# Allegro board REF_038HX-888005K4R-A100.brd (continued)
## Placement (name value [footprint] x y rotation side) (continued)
UNK2RP9  0-5-S4  [R0402]  213.98 216.67 180 bottom
UNK2RP10  0-5-S4  [R0402]  209.43 223.09 270 bottom
UNK2RP11  0-5-S4  [R0402]  202.16 223.09 270 bottom
UNK2RP12  0-5-S4  [R0402]  197.86 218.83 0 bottom
UNK2RT1  10K-1-S4  [R0402]  228.07 244.22 0 top
UNK2RT2  10K-1-S4  [R0402]  228.07 245.49 0 top
UNK2RT3  10K-1-S4  [R0402]  228.07 241.81 180 top
UNK2RT4  10K-1-S4  [R0402]  228.07 240.67 180 top
UNK2RT5  NC/10K-1-S4  [R0402]  228.07 242.95 180 top
UNK2RT6  NC/10K-1-S4  [R0402]  239.63 245.49 180 top
UNK2RT7  NC/10K-1-S4  [R0402]  239.63 242.95 180 top
UNK2RT8  NC/10K-1-S4  [R0402]  239.63 241.68 180 top
UNK2RT9  RTD-100-S8  [R0805]  229.15 205.62 90 top
UNK2RT10  0-5-S8  [R0805]  229.13 201.86 90 top
UNK2S1_I2C  HDR-4X1-MR-A  [JP_4P_100_R90_V1]  264 157.51 0 top
UNK2S1_RST_N  HDR-2X1-M  [JP_2P_100]  258.5 194.46 180 bottom
UNK2SK1  UA2-5NJ-A-V3  [RL_NECUA2_5V_V3]  252.24 183.98 270 bottom
UNK2SK2  UA2-5NJ-A-V3  [RL_NECUA2_5V_V3]  268.75 183.98 270 bottom
UNK2TP_AUXVCC  TP01  [TP_040_T]  47.18 295.44 180 top
UNK2TP_AVDD11_RX  TP01  [TP_040_T]  19.24 284.81 180 top
UNK2TP_AVDD11_XTAL  TP01  [TP_040_T]  45.28 262.58 0 top
UNK2TP_AVDD18_RX  TP01  [TP_040_T]  28.97 284.81 0 top
UNK2TP_PLL_M_VDD33  TP01  [TP_040_T]  45.28 244.17 0 top
UNK2TP_PLL_TX_VDD33  TP01  [TP_040_T]  35.55 244.17 180 top
UNK2TP_VCC3V3  TP01  [TP_040_T]  35.47 295.51 180 top
UNK2TP_VDD_IO_33  TP01  [TP_040_T]  35.55 284.81 180 top
UNK2TP_VDD_TXREG_33_B  TP01  [TP_040_T]  28.97 244.17 0 top
UNK2TP_VDD_TXREG_33_T  TP01  [TP_040_T]  19.24 244.17 180 top
UNK2TP_VDDA_33_LV  TP01  [TP_040_T]  45.28 284.81 0 top
UNK2TP_VDDC_11  TP01  [TP_040_T]  28.97 223.85 0 top
UNK2TP_VDDTXPST_11_B  TP01  [TP_040_T]  28.97 264.49 0 top
UNK2TP_VDDTXPST_11_T  TP01  [TP_040_T]  19.24 264.49 180 top
UNK2TP_XTAL_IN  TP01  [TP_040_T]  182.86 243.18 0 top
UNK2TP_XTAL_OUT  TP01  [TP_040_T]  182.86 248.48 0 top
UNK2U1  SOLDER-DIP8-SOCKET  [DIP8_300X100_RLPIN]  258.26 176.56 180 bottom
UNK2U2  SOLDER-DIP8-SOCKET  [DIP8_300X100_RLPIN]  277.97 176.56 180 bottom
UNK2UT1  ADT7410TRZ-SO8  [SO8_244X127MM]  233.92 243.59 0 top
UNK2Y1  XTAL27M-S2520-ABRACON-10P  [XTAL_2X2P5MM_4P]  174.77 246.4 270 bottom
UNK2Y2  NC/XTAL27M-S3225-TXC-10P  [XTAL_3P2X2P5MM_4P_TXC_0201]  174.77 246.4 270 bottom
UNK038HX-888005K4R-A100  REF-CODE-PCB  [PCB_CODE]  -1.03 116.16 0 top
UNK980HX-888005-KBH-  REF-CODE-PCB  [PCB_CODE]  -17 217.75 0 top
UT1  ADT7410TRZ-SO8  [SO8_244X127MM]  153.92 243.59 0 top
UT_UP5V  TP01  [TP_040_T]  20.37 142.21 270 top
UTL1  V93K_UTL  [PG_VG93K_F_G3UTI1]  35.83 16.51 0 top
UTL2  V93K_UTL  [PG_VG93K_F_G1UTI2]  183.15 16.51 0 top
UTL3  V93K_UTL  [PG_VG93K_F_G2UTI3]  256.81 412.75 0 top
UTL4  V93K_UTL  [PG_VG93K_F_G8UTI4]  109.49 412.75 0 top
Y1  XTAL27M-S2520-ABRACON-10P  [XTAL_2X2P5MM_4P]  94.77 246.4 270 bottom
Y2  NC/XTAL27M-S3225-TXC-10P  [XTAL_3P2X2P5MM_4P_TXC_0201]  94.77 246.4 270 bottom

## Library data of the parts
2SH1-2SH28 SB1-SB3 SB8 SH1-SH28 = SHORT: User Part Number: PNXXXXXXXXXX; Tolerance: TOL
BD29-BD40 = BD120-3A-S8: User Part Number: PNXXXXXXXXXX; Tolerance: TOL
BR902 = 330-1-S4: User Part Number: PNXXXXXXXXXX; Tolerance: TOL
C3 C4 C7-C9 CB1 CB3 CB5 CB7 CB19 CT1 UNK2C3 UNK2C4 UNK2C7-UNK2C9 UNK2CT1 = 0.1U-16-X-S4-MU: User Part Number: PNXXXXXXXXXX; Tolerance: TOL
C5 C6 UNK2C5 UNK2C6 = 22P-50-N-S4-AVX: User Part Number: PNXXXXXXXXXX; Tolerance: TOL
CA1 CA3 CA5 CA7 CA9 CA11 CA14 CA16 CA18 CA20-CA29 CA31 CA32 CA34 CA35 CA37 CA38 CA40 UNK2CA1 UNK2CA3 UNK2CA5 UNK2CA7 UNK2CA9 UNK2CA11 UNK2CA14 UNK2CA16 UNK2CA18 UNK2CA20-UNK2CA29 UNK2CA31 UNK2CA32 UNK2CA34 UNK2CA35 UNK2CA37 UNK2CA38 UNK2CA40 = 10U-10-X6S-S6-MU: User Part Number: PNXXXXXXXXXX; Tolerance: TOL
CA2 CA4 CA6 CA8 CA10 CA12 CA13 CA15 CA17 CA19 CA30 CA33 CA36 CA39 UNK2CA2 UNK2CA4 UNK2CA6 UNK2CA8 UNK2CA10 UNK2CA12 UNK2CA13 UNK2CA15 UNK2CA17 UNK2CA19 UNK2CA30 UNK2CA33 UNK2CA36 UNK2CA39 = 47U-10-X5R-S8-TDK: User Part Number: PNXXXXXXXXXX; Tolerance: TOL
CB2 CB4 CB6 CB8 = 10U-25-X-S6: User Part Number: PNXXXXXXXXXX; Tolerance: TOL
CC1 CC4 CC6-CC9 CC11 CC13 CC19 CC22 CC25-CC37 CC39 UNK2CC1 UNK2CC4 UNK2CC6-UNK2CC9 UNK2CC11 UNK2CC13 UNK2CC19 UNK2CC22 UNK2CC25-UNK2CC37 UNK2CC39 = 0.47U-10-X6S-S2-TY: User Part Number: PNXXXXXXXXXX; Tolerance: TOL
CC2 CC20 CC23 UNK2CC2 UNK2CC20 UNK2CC23 = 4.7U-10-X6T-S4-MU: User Part Number: PNXXXXXXXXXX; Tolerance: TOL
CC15-CC17 CC38 CC40-CC42 UNK2CC15-UNK2CC17 UNK2CC38 UNK2CC40-UNK2CC42 = 4.7U-2.5-X6S-S2-MU: User Part Number: PNXXXXXXXXXX; Tolerance: TOL
CD1 CD3-CD25 UNK2CD1 UNK2CD3-UNK2CD25 = 0.1U-10-X7R-S2-MU: User Part Number: PNXXXXXXXXXX; Tolerance: TOL
CSDPS225 CSDPS229 CSDPS425 CSDPS429 = V93K_CSDPS_DPS32: User Part Number: PNXXXXXXXXXX; Tolerance: TOL
D101/D501 D105/D505 = V93K_PS1600_HD: User Part Number: PNXXXXXXXXXX; Tolerance: TOL
D102-D104 D106-D124 D226-D228 D230-D232 D301 D302 D305 D306 D426-D428 D430-D432 = V93K_CH: Tolerance: TOL; User Part Number: PNXXXXXXXXXX
DPS1-DPS3 DPS8 = V93K_DPS: Tolerance: TOL; User Part Number: PNXXXXXXXXXX
FD1-FD8 = FD_040_V2: Tolerance: TOL; User Part Number: PNXXXXXXXXXX
GND1-GND14 SK1_2-SK1_7 SK2_2-SK2_7 TP_AUXVCC TP_AVDD11_RX TP_AVDD11_XTAL TP_AVDD18_RX TP_PLL_M_VDD33 TP_PLL_TX_VDD33 TP_VCC3V3 TP_VDD_IO_33 TP_VDD_TXREG_33_B TP_VDD_TXREG_33_T TP_VDDA_33_LV TP_VDDC_11 TP_VDDTXPST_11_B TP_VDDTXPST_11_T TP_XTAL_IN TP_XTAL_OUT UNK1SK1_2-UNK1SK1_7 UNK1SK2_2-UNK1SK2_7 UNK2GND1-UNK2GND14 UNK2TP_AUXVCC UNK2TP_AVDD11_RX UNK2TP_AVDD11_XTAL UNK2TP_AVDD18_RX UNK2TP_PLL_M_VDD33 UNK2TP_PLL_TX_VDD33 UNK2TP_VCC3V3 UNK2TP_VDD_IO_33 UNK2TP_VDD_TXREG_33_B UNK2TP_VDD_TXREG_33_T UNK2TP_VDDA_33_LV UNK2TP_VDDC_11 UNK2TP_VDDTXPST_11_B UNK2TP_VDDTXPST_11_T UNK2TP_XTAL_IN UNK2TP_XTAL_OUT UT_UP5V = TP01: Tolerance: TOL; User Part Number: PNXXXXXXXXXX
HX8880-F05 LQFP176-20X20-P0.4 = REF-CODE-CHIP
J1 J4 J5 S1_RST_N UNK2J1 UNK2J4 UNK2J5 UNK2S1_RST_N = HDR-2X1-M: Tolerance: TOL; User Part Number: PNXXXXXXXXXX
J2 J3 UNK2J2 UNK2J3 = HDR-3X1-M: Tolerance: TOL; User Part Number: PNXXXXXXXXXX
JG_220919AA01 JG_220919AA02 = REF-CODE-SOCKET
K1-K8 K11 K16 K17 K21-K27 K29 K30 UNK2K1-UNK2K8 UNK2K11 UNK2K16 UNK2K17 UNK2K21-UNK2K27 UNK2K29 UNK2K30 = G6K-2F-RF-5V-A: Tolerance: TOL; User Part Number: PNXXXXXXXXXX
K9 K10 K12-K15 K19 K20 K28 K33 SK1 SK2 UNK2K9 UNK2K10 UNK2K12-UNK2K15 UNK2K19 UNK2K20 UNK2K28 UNK2K33 UNK2SK1 UNK2SK2 = UA2-5NJ-A-V3: Tolerance: TOL; User Part Number: PNXXXXXXXXXX
K18 UNK2K18 = UB2-5NU-B: Tolerance: TOL; User Part Number: PNXXXXXXXXXX
K31 K34 K36 K37 K39 K40 K42 UNK2K31 UNK2K34 UNK2K36 UNK2K37 UNK2K39 UNK2K40 UNK2K42 = EC2-5NJ-A: Tolerance: TOL; User Part Number: PNXXXXXXXXXX
LD902 = LDG-2-S8: User Part Number: PNXXXXXXXXXX; Tolerance: TOL
LOGO1 = LOGO_KT_KSMT
LOGO2 = LOGO_HX_Himax
R1 R2 R6 UNK2R1 UNK2R2 UNK2R6 = 1M-1-S4: User Part Number: PNXXXXXXXXXX; Tolerance: TOL
R3 R4 R85 UNK2R3 UNK2R4 UNK2R85 = 100K-1-S4: User Part Number: PNXXXXXXXXXX; Tolerance: TOL
R5 R118 R125-R130 R133 RP1-RP12 UNK2R5 UNK2R118 UNK2R125-UNK2R130 UNK2R133 UNK2RP1-UNK2RP12 = 0-5-S4: User Part Number: PNXXXXXXXXXX; Tolerance: TOL
R7-R80 R100-R105 UNK2R7-UNK2R80 UNK2R100-UNK2R105 = 49.9-1-S4: User Part Number: PNXXXXXXXXXX; Tolerance: TOL
R82-R84 R86-R99 R119 R120 UNK2R82-UNK2R84 UNK2R86-UNK2R99 UNK2R119 UNK2R120 = 4.7K-1-S4-WA: User Part Number: PNXXXXXXXXXX; Tolerance: TOL
R117 UNK2R117 = 1K-1-S4: User Part Number: PNXXXXXXXXXX; Tolerance: TOL
R131 R132 UNK2R131 UNK2R132 = 50-0.1-S4-HF-VI: User Part Number: PNXXXXXXXXXX; Tolerance: TOL
RB1 RB2 = 10K-1-S6: User Part Number: PNXXXXXXXXXX; Tolerance: TOL
RT1-RT8 UNK2RT1-UNK2RT8 = 10K-1-S4: User Part Number: PNXXXXXXXXXX; Tolerance: TOL
RT9 UNK2RT9 = RTD-100-S8: User Part Number: PNXXXXXXXXXX; Tolerance: TOL
RT10 UNK2RT10 = 0-5-S8: User Part Number: PNXXXXXXXXXX; Tolerance: TOL
S1_I2C UNK2S1_I2C = HDR-4X1-MR-A: Tolerance: TOL; User Part Number: PNXXXXXXXXXX
SCREW1 = V93KHSCREW: Tolerance: TOL; User Part Number: PNXXXXXXXXXX
SITE1 SITE2 = CU/HX8880-F05-LQFP176-20X20: User Part Number: PNXXXXXXXXXX; Tolerance: TOL
SKB1 = V93K_SKB_140X140MM: Tolerance: TOL; User Part Number: PNXXXXXXXXXX
SW1 = SW-TACTILE-1-D4.5: Tolerance: TOL; User Part Number: PNXXXXXXXXXX
TPL1-TPL20 = TPL01: Tolerance: TOL; User Part Number: PNXXXXXXXXXX
U1 U2 UNK2U1 UNK2U2 = MX25V4006EM1I-13G-SO8: User Part Number: PNXXXXXXXXXX; Tolerance: TOL
UB1 = AT24C08-D: User Part Number: PNXXXXXXXXXX; Tolerance: TOL
UNK2UT1 UT1 = ADT7410: Tolerance: TOL; User Part Number: PNXXXXXXXXXX
UNK2Y1 Y1 = XTAL27M-S2520-ABRACON-10P: User Part Number: PNXXXXXXXXXX; Tolerance: TOL
UNK2Y2 Y2 = XTAL27M-S3225-TXC-10P: User Part Number: PNXXXXXXXXXX; Tolerance: TOL
UNK038HX-888005K4R-A100 UNK980HX-888005-KBH- = REF-CODE-PCB
UTL1-UTL4 = V93K_UTL: User Part Number: PNXXXXXXXXXX; Tolerance: TOL

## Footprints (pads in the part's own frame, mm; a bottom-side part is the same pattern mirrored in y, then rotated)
C0201
  rect 0.305x0.356 smd: 1(-0.3,0) 2(0.3,0)
C0402
  custom 0.15x0.15 smd: 1(-0.5,0) 2(0.5,0)
C0603
  rect 0.889x0.889 smd: 1(-0.85,0) 2(0.85,0)
C0805
  rect 1.118x1.372 smd: 1(-0.95,0) 2(0.95,0)
CHIP_CODE
  round 0.051 smd: 1(0,0)
DEFAULT_SHORT_SMALL
  custom 0.07x0.07 smd: 1(-0.5,0) 2(0.5,0)
DIP8_300X100_RLPIN
  rect 1.524x1.524 hole 1.041: 1(0,0)
  round 1.524 hole 1.041: 2(0,-2.54) 3(0,-5.08) 4(0,-7.62) 5(7.62,-7.62) 6(7.62,-5.08) 7(7.62,-2.54) 8(7.62,0)
FB0805
  rect 1.118x1.372 smd: 1(-0.965,0) 2(0.965,0)
FD_040_V2
  round 1.016 smd: 1(0,0)
JP_2P_100
  rect 1.524x1.524 hole 1.016: 1(0,0)
  round 1.524 hole 1.016: 2(0,2.54)
JP_3P_100
  rect 1.524x1.524 hole 1.016: 1(0,0)
  round 1.524 hole 1.016: 2(0,2.54) 3(0,5.08)
JP_4P_100_R90_V1
  rect 1.524x1.524 hole 1.016: 1(0,0)
  round 1.524 hole 1.016: 2(0,2.54) 3(0,5.08) 4(0,7.62)
LED_0805
  rect 1.118x1.372 smd: 1(0.95,0) 2(-0.95,0)
LOGO_HX_HIMAX
  round 0.051 smd: 1(0.831,1.487)
LOGO_KT_KSMT
  round 0.051 smd: 1(-0.711,-0.711)
PCB_CODE
  round 0.051 smd: 1(0,0)
PG_VG93K_F_G1D102
  round 1.778 hole 0.711: 01(-20.32,-1.27) 02(-17.78,1.27) 03(-15.24,-1.27) 04(-12.7,1.27) 05(-10.16,-1.27) 06(-7.62,1.27) 07(-5.08,-1.27) 08(-2.54,1.27) 09(0,-1.27) 10(2.54,1.27) 11(5.08,-1.27) 12(7.62,1.27) 13(10.16,-1.27) 14(12.7,1.27) 15(15.24,-1.27) 16(17.78,1.27) 17(20.32,-1.27)
  rect 1.778x1.778 hole 0.711: A1(-20.32,-3.81) A2(-17.78,-1.27) A3(-15.24,-3.81) A4(-12.7,-1.27) A5(-10.16,-3.81) A6(-7.62,-1.27) A7(-5.08,-3.81) A8(-2.54,-1.27) A9(0,-3.81) A10(2.54,-1.27) A11(5.08,-3.81) A12(7.62,-1.27) A13(10.16,-3.81) A14(12.7,-1.27) A15(15.24,-3.81) A16(17.78,-1.27) A17(20.32,-3.81) B1(-20.32,1.27) B2(-17.78,3.81) B3(-15.24,1.27) B4(-12.7,3.81) B5(-10.16,1.27) B6(-7.62,3.81) B7(-5.08,1.27) B8(-2.54,3.81) B9(0,1.27) B10(2.54,3.81) B11(5.08,1.27) B12(7.62,3.81) B13(10.16,1.27) B14(12.7,3.81) B15(15.24,1.27) B16(17.78,3.81) B17(20.32,1.27)
PG_VG93K_F_G1D103
  round 1.778 hole 0.711: 01(-20.32,-1.27) 02(-17.78,1.27) 03(-15.24,-1.27) 04(-12.7,1.27) 05(-10.16,-1.27) 06(-7.62,1.27) 07(-5.08,-1.27) 08(-2.54,1.27) 09(0,-1.27) 10(2.54,1.27) 11(5.08,-1.27) 12(7.62,1.27) 13(10.16,-1.27) 14(12.7,1.27) 15(15.24,-1.27) 16(17.78,1.27) 17(20.32,-1.27)
  rect 1.778x1.778 hole 0.711: A1(-20.32,-3.81) A2(-17.78,-1.27) A3(-15.24,-3.81) A4(-12.7,-1.27) A5(-10.16,-3.81) A6(-7.62,-1.27) A7(-5.08,-3.81) A8(-2.54,-1.27) A9(0,-3.81) A10(2.54,-1.27) A11(5.08,-3.81) A12(7.62,-1.27) A13(10.16,-3.81) A14(12.7,-1.27) A15(15.24,-3.81) A16(17.78,-1.27) A17(20.32,-3.81) B1(-20.32,1.27) B2(-17.78,3.81) B3(-15.24,1.27) B4(-12.7,3.81) B5(-10.16,1.27) B6(-7.62,3.81) B7(-5.08,1.27) B8(-2.54,3.81) B9(0,1.27) B10(2.54,3.81) B11(5.08,1.27) B12(7.62,3.81) B13(10.16,1.27) B14(12.7,3.81) B15(15.24,1.27) B16(17.78,3.81) B17(20.32,1.27)
PG_VG93K_F_G1D104
  round 1.778 hole 0.711: 01(-20.32,-1.27) 02(-17.78,1.27) 03(-15.24,-1.27) 04(-12.7,1.27) 05(-10.16,-1.27) 06(-7.62,1.27) 07(-5.08,-1.27) 08(-2.54,1.27) 09(0,-1.27) 10(2.54,1.27) 11(5.08,-1.27) 12(7.62,1.27) 13(10.16,-1.27) 14(12.7,1.27) 15(15.24,-1.27) 16(17.78,1.27) 17(20.32,-1.27)
  rect 1.778x1.778 hole 0.711: A1(-20.32,-3.81) A2(-17.78,-1.27) A3(-15.24,-3.81) A4(-12.7,-1.27) A5(-10.16,-3.81) A6(-7.62,-1.27) A7(-5.08,-3.81) A8(-2.54,-1.27) A9(0,-3.81) A10(2.54,-1.27) A11(5.08,-3.81) A12(7.62,-1.27) A13(10.16,-3.81) A14(12.7,-1.27) A15(15.24,-3.81) A16(17.78,-1.27) A17(20.32,-3.81) B1(-20.32,1.27) B2(-17.78,3.81) B3(-15.24,1.27) B4(-12.7,3.81) B5(-10.16,1.27) B6(-7.62,3.81) B7(-5.08,1.27) B8(-2.54,3.81) B9(0,1.27) B10(2.54,3.81) B11(5.08,1.27) B12(7.62,3.81) B13(10.16,1.27) B14(12.7,3.81) B15(15.24,1.27) B16(17.78,3.81) B17(20.32,1.27)
PG_VG93K_F_G1D106
  round 1.778 hole 0.711: 01(-20.32,-1.27) 02(-17.78,1.27) 03(-15.24,-1.27) 04(-12.7,1.27) 05(-10.16,-1.27) 06(-7.62,1.27) 07(-5.08,-1.27) 08(-2.54,1.27) 09(0,-1.27) 10(2.54,1.27) 11(5.08,-1.27) 12(7.62,1.27) 13(10.16,-1.27) 14(12.7,1.27) 15(15.24,-1.27) 16(17.78,1.27) 17(20.32,-1.27)
  rect 1.778x1.778 hole 0.711: A1(-20.32,-3.81) A2(-17.78,-1.27) A3(-15.24,-3.81) A4(-12.7,-1.27) A5(-10.16,-3.81) A6(-7.62,-1.27) A7(-5.08,-3.81) A8(-2.54,-1.27) A9(0,-3.81) A10(2.54,-1.27) A11(5.08,-3.81) A12(7.62,-1.27) A13(10.16,-3.81) A14(12.7,-1.27) A15(15.24,-3.81) A16(17.78,-1.27) A17(20.32,-3.81) B1(-20.32,1.27) B2(-17.78,3.81) B3(-15.24,1.27) B4(-12.7,3.81) B5(-10.16,1.27) B6(-7.62,3.81) B7(-5.08,1.27) B8(-2.54,3.81) B9(0,1.27) B10(2.54,3.81) B11(5.08,1.27) B12(7.62,3.81) B13(10.16,1.27) B14(12.7,3.81) B15(15.24,1.27) B16(17.78,3.81) B17(20.32,1.27)
PG_VG93K_F_G1D107
  round 1.778 hole 0.711: 01(-20.32,-1.27) 02(-17.78,1.27) 03(-15.24,-1.27) 04(-12.7,1.27) 05(-10.16,-1.27) 06(-7.62,1.27) 07(-5.08,-1.27) 08(-2.54,1.27) 09(0,-1.27) 10(2.54,1.27) 11(5.08,-1.27) 12(7.62,1.27) 13(10.16,-1.27) 14(12.7,1.27) 15(15.24,-1.27) 16(17.78,1.27) 17(20.32,-1.27)
  rect 1.778x1.778 hole 0.711: A1(-20.32,-3.81) A2(-17.78,-1.27) A3(-15.24,-3.81) A4(-12.7,-1.27) A5(-10.16,-3.81) A6(-7.62,-1.27) A7(-5.08,-3.81) A8(-2.54,-1.27) A9(0,-3.81) A10(2.54,-1.27) A11(5.08,-3.81) A12(7.62,-1.27) A13(10.16,-3.81) A14(12.7,-1.27) A15(15.24,-3.81) A16(17.78,-1.27) A17(20.32,-3.81) B1(-20.32,1.27) B2(-17.78,3.81) B3(-15.24,1.27) B4(-12.7,3.81) B5(-10.16,1.27) B6(-7.62,3.81) B7(-5.08,1.27) B8(-2.54,3.81) B9(0,1.27) B10(2.54,3.81) B11(5.08,1.27) B12(7.62,3.81) B13(10.16,1.27) B14(12.7,3.81) B15(15.24,1.27) B16(17.78,3.81) B17(20.32,1.27)
PG_VG93K_F_G1D108
  round 1.778 hole 0.711: 01(-20.32,-1.27) 02(-17.78,1.27) 03(-15.24,-1.27) 04(-12.7,1.27) 05(-10.16,-1.27) 06(-7.62,1.27) 07(-5.08,-1.27) 08(-2.54,1.27) 09(0,-1.27) 10(2.54,1.27) 11(5.08,-1.27) 12(7.62,1.27) 13(10.16,-1.27) 14(12.7,1.27) 15(15.24,-1.27) 16(17.78,1.27) 17(20.32,-1.27)
  rect 1.778x1.778 hole 0.711: A1(-20.32,-3.81) A2(-17.78,-1.27) A3(-15.24,-3.81) A4(-12.7,-1.27) A5(-10.16,-3.81) A6(-7.62,-1.27) A7(-5.08,-3.81) A8(-2.54,-1.27) A9(0,-3.81) A10(2.54,-1.27) A11(5.08,-3.81) A12(7.62,-1.27) A13(10.16,-3.81) A14(12.7,-1.27) A15(15.24,-3.81) A16(17.78,-1.27) A17(20.32,-3.81) B1(-20.32,1.27) B2(-17.78,3.81) B3(-15.24,1.27) B4(-12.7,3.81) B5(-10.16,1.27) B6(-7.62,3.81) B7(-5.08,1.27) B8(-2.54,3.81) B9(0,1.27) B10(2.54,3.81) B11(5.08,1.27) B12(7.62,3.81) B13(10.16,1.27) B14(12.7,3.81) B15(15.24,1.27) B16(17.78,3.81) B17(20.32,1.27)
PG_VG93K_F_G1D301
  round 1.778 hole 0.711: 01(-20.32,-1.27) 03(-15.24,-1.27) 05(-10.16,-1.27) 07(-5.08,-1.27) 09(0,-1.27) 11(5.08,-1.27) 13(10.16,-1.27) 15(15.24,-1.27) 17(20.32,-1.27)
  round 0.66 hole 0.356: 02(-17.78,1.27) 04(-12.7,1.27) 06(-7.62,1.27) 08(-2.54,1.27) 10(2.54,1.27) 12(7.62,1.27) 14(12.7,1.27) 16(17.78,1.27)
  rect 1.778x1.778 hole 0.711: A1(-20.32,-3.81) A2(-17.78,-1.27) A3(-15.24,-3.81) A4(-12.7,-1.27) A5(-10.16,-3.81) A6(-7.62,-1.27) A7(-5.08,-3.81) A8(-2.54,-1.27) A9(0,-3.81) A10(2.54,-1.27) A11(5.08,-3.81) A12(7.62,-1.27) A13(10.16,-3.81) A14(12.7,-1.27) A15(15.24,-3.81) A16(17.78,-1.27) A17(20.32,-3.81) B1(-20.32,1.27) B2(-17.78,3.81) B3(-15.24,1.27) B4(-12.7,3.81) B5(-10.16,1.27) B6(-7.62,3.81) B7(-5.08,1.27) B8(-2.54,3.81) B9(0,1.27) B10(2.54,3.81) B11(5.08,1.27) B12(7.62,3.81) B13(10.16,1.27) B14(12.7,3.81) B15(15.24,1.27) B16(17.78,3.81) B17(20.32,1.27)
PG_VG93K_F_G1D302
  round 1.778 hole 0.711: 01(-20.32,-1.27) 02(-17.78,1.27) 03(-15.24,-1.27) 04(-12.7,1.27) 05(-10.16,-1.27) 06(-7.62,1.27) 07(-5.08,-1.27) 08(-2.54,1.27) 09(0,-1.27) 10(2.54,1.27) 11(5.08,-1.27) 12(7.62,1.27) 13(10.16,-1.27) 14(12.7,1.27) 15(15.24,-1.27) 16(17.78,1.27) 17(20.32,-1.27)
  rect 1.778x1.778 hole 0.711: A1(-20.32,-3.81) A2(-17.78,-1.27) A3(-15.24,-3.81) A4(-12.7,-1.27) A5(-10.16,-3.81) A6(-7.62,-1.27) A7(-5.08,-3.81) A8(-2.54,-1.27) A9(0,-3.81) A10(2.54,-1.27) A11(5.08,-3.81) A12(7.62,-1.27) A13(10.16,-3.81) A14(12.7,-1.27) A15(15.24,-3.81) A16(17.78,-1.27) A17(20.32,-3.81) B1(-20.32,1.27) B2(-17.78,3.81) B3(-15.24,1.27) B4(-12.7,3.81) B5(-10.16,1.27) B6(-7.62,3.81) B7(-5.08,1.27) B8(-2.54,3.81) B9(0,1.27) B10(2.54,3.81) B11(5.08,1.27) B12(7.62,3.81) B13(10.16,1.27) B14(12.7,3.81) B15(15.24,1.27) B16(17.78,3.81) B17(20.32,1.27)
PG_VG93K_F_G1D305
  round 1.778 hole 0.711: 01(-20.32,-1.27) 03(-15.24,-1.27) 05(-10.16,-1.27) 07(-5.08,-1.27) 09(0,-1.27) 11(5.08,-1.27) 13(10.16,-1.27) 15(15.24,-1.27) 17(20.32,-1.27)
  round 0.66 hole 0.356: 02(-17.78,1.27) 04(-12.7,1.27) 06(-7.62,1.27) 08(-2.54,1.27) 10(2.54,1.27) 12(7.62,1.27) 14(12.7,1.27) 16(17.78,1.27)
  rect 1.778x1.778 hole 0.711: A1(-20.32,-3.81) A2(-17.78,-1.27) A3(-15.24,-3.81) A4(-12.7,-1.27) A5(-10.16,-3.81) A6(-7.62,-1.27) A7(-5.08,-3.81) A8(-2.54,-1.27) A9(0,-3.81) A10(2.54,-1.27) A11(5.08,-3.81) A12(7.62,-1.27) A13(10.16,-3.81) A14(12.7,-1.27) A15(15.24,-3.81) A16(17.78,-1.27) A17(20.32,-3.81) B1(-20.32,1.27) B2(-17.78,3.81) B3(-15.24,1.27) B4(-12.7,3.81) B5(-10.16,1.27) B6(-7.62,3.81) B7(-5.08,1.27) B8(-2.54,3.81) B9(0,1.27) B10(2.54,3.81) B11(5.08,1.27) B12(7.62,3.81) B13(10.16,1.27) B14(12.7,3.81) B15(15.24,1.27) B16(17.78,3.81) B17(20.32,1.27)
PG_VG93K_F_G1D306
  round 1.778 hole 0.711: 01(-20.32,-1.27) 02(-17.78,1.27) 03(-15.24,-1.27) 04(-12.7,1.27) 05(-10.16,-1.27) 06(-7.62,1.27) 07(-5.08,-1.27) 08(-2.54,1.27) 09(0,-1.27) 10(2.54,1.27) 11(5.08,-1.27) 12(7.62,1.27) 13(10.16,-1.27) 14(12.7,1.27) 15(15.24,-1.27) 16(17.78,1.27) 17(20.32,-1.27)
  rect 1.778x1.778 hole 0.711: A1(-20.32,-3.81) A2(-17.78,-1.27) A3(-15.24,-3.81) A4(-12.7,-1.27) A5(-10.16,-3.81) A6(-7.62,-1.27) A7(-5.08,-3.81) A8(-2.54,-1.27) A9(0,-3.81) A10(2.54,-1.27) A11(5.08,-3.81) A12(7.62,-1.27) A13(10.16,-3.81) A14(12.7,-1.27) A15(15.24,-3.81) A16(17.78,-1.27) A17(20.32,-3.81) B1(-20.32,1.27) B2(-17.78,3.81) B3(-15.24,1.27) B4(-12.7,3.81) B5(-10.16,1.27) B6(-7.62,3.81) B7(-5.08,1.27) B8(-2.54,3.81) B9(0,1.27) B10(2.54,3.81) B11(5.08,1.27) B12(7.62,3.81) B13(10.16,1.27) B14(12.7,3.81) B15(15.24,1.27) B16(17.78,3.81) B17(20.32,1.27)
PG_VG93K_F_G1DPS1
  round 1.778 hole 0.711: A01(-20.32,-2.54) A02(-17.78,-2.54) A03(-15.24,-2.54) A04(-12.7,-2.54) A05(-10.16,-2.54) A06(-7.62,-2.54) A07(-5.08,-2.54) A08(-2.54,-2.54) A09(0,-2.54) A10(2.54,-2.54) A11(5.08,-2.54) A12(7.62,-2.54) A13(10.16,-2.54) A14(12.7,-2.54) A15(15.24,-2.54) A16(17.78,-2.54) A17(20.32,-2.54) B01(-20.32,0) B02(-17.78,0) B03(-15.24,0) B04(-12.7,0) B05(-10.16,0) B06(-7.62,0) B07(-5.08,0) B08(-2.54,0) B09(0,0) B10(2.54,0) B11(5.08,0) B12(7.62,0) B13(10.16,0) B14(12.7,0) B15(15.24,0) B16(17.78,0) B17(20.32,0) C01(-20.32,2.54) C02(-17.78,2.54) C03(-15.24,2.54) C04(-12.7,2.54) C05(-10.16,2.54) C06(-7.62,2.54) C07(-5.08,2.54) C08(-2.54,2.54) C09(0,2.54) C10(2.54,2.54) C11(5.08,2.54) C12(7.62,2.54) C13(10.16,2.54) C14(12.7,2.54) C15(15.24,2.54) C16(17.78,2.54) C17(20.32,2.54)
PG_VG93K_F_G1UTI2
  round 1.778 hole 0.711: A01(-20.32,-1.27) A02(-17.78,-1.27) A03(-15.24,-1.27) A04(-12.7,-1.27) A05(-10.16,-1.27) A06(-7.62,-1.27) A07(-5.08,-1.27) A08(-2.54,-1.27) A09(0,-1.27) A10(2.54,-1.27) A11(5.08,-1.27) A12(7.62,-1.27) A13(10.16,-1.27) A14(12.7,-1.27) A15(15.24,-1.27) A16(17.78,-1.27) A17(20.32,-1.27) B01(-20.32,1.27) B02(-17.78,1.27) B03(-15.24,1.27) B04(-12.7,1.27) B05(-10.16,1.27) B06(-7.62,1.27) B07(-5.08,1.27) B08(-2.54,1.27) B09(0,1.27) B10(2.54,1.27) B11(5.08,1.27) B12(7.62,1.27) B13(10.16,1.27) B14(12.7,1.27) B15(15.24,1.27) B16(17.78,1.27) B17(20.32,1.27)
PG_VG93K_F_G2D109
  round 1.778 hole 0.711: 01(20.32,1.27) 02(17.78,-1.27) 03(15.24,1.27) 04(12.7,-1.27) 05(10.16,1.27) 06(7.62,-1.27) 07(5.08,1.27) 08(2.54,-1.27) 09(0,1.27) 10(-2.54,-1.27) 11(-5.08,1.27) 12(-7.62,-1.27) 13(-10.16,1.27) 14(-12.7,-1.27) 15(-15.24,1.27) 16(-17.78,-1.27) 17(-20.32,1.27)
  rect 1.778x1.778 hole 0.711: A1(20.32,3.81) A2(17.78,1.27) A3(15.24,3.81) A4(12.7,1.27) A5(10.16,3.81) A6(7.62,1.27) A7(5.08,3.81) A8(2.54,1.27) A9(0,3.81) A10(-2.54,1.27) A11(-5.08,3.81) A12(-7.62,1.27) A13(-10.16,3.81) A14(-12.7,1.27) A15(-15.24,3.81) A16(-17.78,1.27) A17(-20.32,3.81) B1(20.32,-1.27) B2(17.78,-3.81) B3(15.24,-1.27) B4(12.7,-3.81) B5(10.16,-1.27) B6(7.62,-3.81) B7(5.08,-1.27) B8(2.54,-3.81) B9(0,-1.27) B10(-2.54,-3.81) B11(-5.08,-1.27) B12(-7.62,-3.81) B13(-10.16,-1.27) B14(-12.7,-3.81) B15(-15.24,-1.27) B16(-17.78,-3.81) B17(-20.32,-1.27)
PG_VG93K_F_G2D110
  round 1.778 hole 0.711: 01(20.32,1.27) 02(17.78,-1.27) 03(15.24,1.27) 04(12.7,-1.27) 05(10.16,1.27) 06(7.62,-1.27) 07(5.08,1.27) 08(2.54,-1.27) 09(0,1.27) 10(-2.54,-1.27) 11(-5.08,1.27) 12(-7.62,-1.27) 13(-10.16,1.27) 14(-12.7,-1.27) 15(-15.24,1.27) 16(-17.78,-1.27) 17(-20.32,1.27)
  rect 1.778x1.778 hole 0.711: A1(20.32,3.81) A2(17.78,1.27) A3(15.24,3.81) A4(12.7,1.27) A5(10.16,3.81) A6(7.62,1.27) A7(5.08,3.81) A8(2.54,1.27) A9(0,3.81) A10(-2.54,1.27) A11(-5.08,3.81) A12(-7.62,1.27) A13(-10.16,3.81) A14(-12.7,1.27) A15(-15.24,3.81) A16(-17.78,1.27) A17(-20.32,3.81) B1(20.32,-1.27) B2(17.78,-3.81) B3(15.24,-1.27) B4(12.7,-3.81) B5(10.16,-1.27) B6(7.62,-3.81) B7(5.08,-1.27) B8(2.54,-3.81) B9(0,-1.27) B10(-2.54,-3.81) B11(-5.08,-1.27) B12(-7.62,-3.81) B13(-10.16,-1.27) B14(-12.7,-3.81) B15(-15.24,-1.27) B16(-17.78,-3.81) B17(-20.32,-1.27)
PG_VG93K_F_G2D111
  round 1.778 hole 0.711: 01(20.32,1.27) 02(17.78,-1.27) 03(15.24,1.27) 04(12.7,-1.27) 05(10.16,1.27) 06(7.62,-1.27) 07(5.08,1.27) 08(2.54,-1.27) 09(0,1.27) 10(-2.54,-1.27) 11(-5.08,1.27) 12(-7.62,-1.27) 13(-10.16,1.27) 14(-12.7,-1.27) 15(-15.24,1.27) 16(-17.78,-1.27) 17(-20.32,1.27)
  rect 1.778x1.778 hole 0.711: A1(20.32,3.81) A2(17.78,1.27) A3(15.24,3.81) A4(12.7,1.27) A5(10.16,3.81) A6(7.62,1.27) A7(5.08,3.81) A8(2.54,1.27) A9(0,3.81) A10(-2.54,1.27) A11(-5.08,3.81) A12(-7.62,1.27) A13(-10.16,3.81) A14(-12.7,1.27) A15(-15.24,3.81) A16(-17.78,1.27) A17(-20.32,3.81) B1(20.32,-1.27) B2(17.78,-3.81) B3(15.24,-1.27) B4(12.7,-3.81) B5(10.16,-1.27) B6(7.62,-3.81) B7(5.08,-1.27) B8(2.54,-3.81) B9(0,-1.27) B10(-2.54,-3.81) B11(-5.08,-1.27) B12(-7.62,-3.81) B13(-10.16,-1.27) B14(-12.7,-3.81) B15(-15.24,-1.27) B16(-17.78,-3.81) B17(-20.32,-1.27)
PG_VG93K_F_G2D112
  round 1.778 hole 0.711: 01(20.32,1.27) 02(17.78,-1.27) 03(15.24,1.27) 04(12.7,-1.27) 05(10.16,1.27) 06(7.62,-1.27) 07(5.08,1.27) 08(2.54,-1.27) 09(0,1.27) 10(-2.54,-1.27) 11(-5.08,1.27) 12(-7.62,-1.27) 13(-10.16,1.27) 14(-12.7,-1.27) 15(-15.24,1.27) 16(-17.78,-1.27) 17(-20.32,1.27)
  rect 1.778x1.778 hole 0.711: A1(20.32,3.81) A2(17.78,1.27) A3(15.24,3.81) A4(12.7,1.27) A5(10.16,3.81) A6(7.62,1.27) A7(5.08,3.81) A8(2.54,1.27) A9(0,3.81) A10(-2.54,1.27) A11(-5.08,3.81) A12(-7.62,1.27) A13(-10.16,3.81) A14(-12.7,1.27) A15(-15.24,3.81) A16(-17.78,1.27) A17(-20.32,3.81) B1(20.32,-1.27) B2(17.78,-3.81) B3(15.24,-1.27) B4(12.7,-3.81) B5(10.16,-1.27) B6(7.62,-3.81) B7(5.08,-1.27) B8(2.54,-3.81) B9(0,-1.27) B10(-2.54,-3.81) B11(-5.08,-1.27) B12(-7.62,-3.81) B13(-10.16,-1.27) B14(-12.7,-3.81) B15(-15.24,-1.27) B16(-17.78,-3.81) B17(-20.32,-1.27)
PG_VG93K_F_G2D113
  round 1.778 hole 0.711: 01(20.32,1.27) 02(17.78,-1.27) 03(15.24,1.27) 04(12.7,-1.27) 05(10.16,1.27) 06(7.62,-1.27) 07(5.08,1.27) 08(2.54,-1.27) 09(0,1.27) 10(-2.54,-1.27) 11(-5.08,1.27) 12(-7.62,-1.27) 13(-10.16,1.27) 14(-12.7,-1.27) 15(-15.24,1.27) 16(-17.78,-1.27) 17(-20.32,1.27)
  rect 1.778x1.778 hole 0.711: A1(20.32,3.81) A2(17.78,1.27) A3(15.24,3.81) A4(12.7,1.27) A5(10.16,3.81) A6(7.62,1.27) A7(5.08,3.81) A8(2.54,1.27) A9(0,3.81) A10(-2.54,1.27) A11(-5.08,3.81) A12(-7.62,1.27) A13(-10.16,3.81) A14(-12.7,1.27) A15(-15.24,3.81) A16(-17.78,1.27) A17(-20.32,3.81) B1(20.32,-1.27) B2(17.78,-3.81) B3(15.24,-1.27) B4(12.7,-3.81) B5(10.16,-1.27) B6(7.62,-3.81) B7(5.08,-1.27) B8(2.54,-3.81) B9(0,-1.27) B10(-2.54,-3.81) B11(-5.08,-1.27) B12(-7.62,-3.81) B13(-10.16,-1.27) B14(-12.7,-3.81) B15(-15.24,-1.27) B16(-17.78,-3.81) B17(-20.32,-1.27)
PG_VG93K_F_G2D114
  round 1.778 hole 0.711: 01(20.32,1.27) 02(17.78,-1.27) 03(15.24,1.27) 04(12.7,-1.27) 05(10.16,1.27) 06(7.62,-1.27) 07(5.08,1.27) 08(2.54,-1.27) 09(0,1.27) 10(-2.54,-1.27) 11(-5.08,1.27) 12(-7.62,-1.27) 13(-10.16,1.27) 14(-12.7,-1.27) 15(-15.24,1.27) 16(-17.78,-1.27) 17(-20.32,1.27)
  rect 1.778x1.778 hole 0.711: A1(20.32,3.81) A2(17.78,1.27) A3(15.24,3.81) A4(12.7,1.27) A5(10.16,3.81) A6(7.62,1.27) A7(5.08,3.81) A8(2.54,1.27) A9(0,3.81) A10(-2.54,1.27) A11(-5.08,3.81) A12(-7.62,1.27) A13(-10.16,3.81) A14(-12.7,1.27) A15(-15.24,3.81) A16(-17.78,1.27) A17(-20.32,3.81) B1(20.32,-1.27) B2(17.78,-3.81) B3(15.24,-1.27) B4(12.7,-3.81) B5(10.16,-1.27) B6(7.62,-3.81) B7(5.08,-1.27) B8(2.54,-3.81) B9(0,-1.27) B10(-2.54,-3.81) B11(-5.08,-1.27) B12(-7.62,-3.81) B13(-10.16,-1.27) B14(-12.7,-3.81) B15(-15.24,-1.27) B16(-17.78,-3.81) B17(-20.32,-1.27)
PG_VG93K_F_G2D115
  round 1.778 hole 0.711: 01(20.32,1.27) 02(17.78,-1.27) 03(15.24,1.27) 04(12.7,-1.27) 05(10.16,1.27) 06(7.62,-1.27) 07(5.08,1.27) 08(2.54,-1.27) 09(0,1.27) 10(-2.54,-1.27) 11(-5.08,1.27) 12(-7.62,-1.27) 13(-10.16,1.27) 14(-12.7,-1.27) 15(-15.24,1.27) 16(-17.78,-1.27) 17(-20.32,1.27)
  rect 1.778x1.778 hole 0.711: A1(20.32,3.81) A2(17.78,1.27) A3(15.24,3.81) A4(12.7,1.27) A5(10.16,3.81) A6(7.62,1.27) A7(5.08,3.81) A8(2.54,1.27) A9(0,3.81) A10(-2.54,1.27) A11(-5.08,3.81) A12(-7.62,1.27) A13(-10.16,3.81) A14(-12.7,1.27) A15(-15.24,3.81) A16(-17.78,1.27) A17(-20.32,3.81) B1(20.32,-1.27) B2(17.78,-3.81) B3(15.24,-1.27) B4(12.7,-3.81) B5(10.16,-1.27) B6(7.62,-3.81) B7(5.08,-1.27) B8(2.54,-3.81) B9(0,-1.27) B10(-2.54,-3.81) B11(-5.08,-1.27) B12(-7.62,-3.81) B13(-10.16,-1.27) B14(-12.7,-3.81) B15(-15.24,-1.27) B16(-17.78,-3.81) B17(-20.32,-1.27)
PG_VG93K_F_G2D116
  round 1.778 hole 0.711: 01(20.32,1.27) 02(17.78,-1.27) 03(15.24,1.27) 04(12.7,-1.27) 05(10.16,1.27) 06(7.62,-1.27) 07(5.08,1.27) 08(2.54,-1.27) 09(0,1.27) 10(-2.54,-1.27) 11(-5.08,1.27) 12(-7.62,-1.27) 13(-10.16,1.27) 14(-12.7,-1.27) 15(-15.24,1.27) 16(-17.78,-1.27) 17(-20.32,1.27)
  rect 1.778x1.778 hole 0.711: A1(20.32,3.81) A2(17.78,1.27) A3(15.24,3.81) A4(12.7,1.27) A5(10.16,3.81) A6(7.62,1.27) A7(5.08,3.81) A8(2.54,1.27) A9(0,3.81) A10(-2.54,1.27) A11(-5.08,3.81) A12(-7.62,1.27) A13(-10.16,3.81) A14(-12.7,1.27) A15(-15.24,3.81) A16(-17.78,1.27) A17(-20.32,3.81) B1(20.32,-1.27) B2(17.78,-3.81) B3(15.24,-1.27) B4(12.7,-3.81) B5(10.16,-1.27) B6(7.62,-3.81) B7(5.08,-1.27) B8(2.54,-3.81) B9(0,-1.27) B10(-2.54,-3.81) B11(-5.08,-1.27) B12(-7.62,-3.81) B13(-10.16,-1.27) B14(-12.7,-3.81) B15(-15.24,-1.27) B16(-17.78,-3.81) B17(-20.32,-1.27)
PG_VG93K_F_G2DPS2
  round 1.778 hole 0.711: A01(20.32,2.54) A02(17.78,2.54) A03(15.24,2.54) A04(12.7,2.54) A05(10.16,2.54) A06(7.62,2.54) A07(5.08,2.54) A08(2.54,2.54) A09(0,2.54) A10(-2.54,2.54) A11(-5.08,2.54) A12(-7.62,2.54) A13(-10.16,2.54) A14(-12.7,2.54) A15(-15.24,2.54) A16(-17.78,2.54) A17(-20.32,2.54) B01(20.32,0) B02(17.78,0) B03(15.24,0) B04(12.7,0) B05(10.16,0) B06(7.62,0) B07(5.08,0) B08(2.54,0) B09(0,0) B10(-2.54,0) B11(-5.08,0) B12(-7.62,0) B13(-10.16,0) B14(-12.7,0) B15(-15.24,0) B16(-17.78,0) B17(-20.32,0) C01(20.32,-2.54) C02(17.78,-2.54) C03(15.24,-2.54) C04(12.7,-2.54) C05(10.16,-2.54) C06(7.62,-2.54) C07(5.08,-2.54) C08(2.54,-2.54) C09(0,-2.54) C10(-2.54,-2.54) C11(-5.08,-2.54) C12(-7.62,-2.54) C13(-10.16,-2.54) C14(-12.7,-2.54) C15(-15.24,-2.54) C16(-17.78,-2.54) C17(-20.32,-2.54)
PG_VG93K_F_G2UTI3
  round 1.778 hole 0.711: A01(20.32,1.27) A02(17.78,1.27) A03(15.24,1.27) A04(12.7,1.27) A05(10.16,1.27) A06(7.62,1.27) A07(5.08,1.27) A08(2.54,1.27) A09(0,1.27) A10(-2.54,1.27) A11(-5.08,1.27) A12(-7.62,1.27) A13(-10.16,1.27) A14(-12.7,1.27) A15(-15.24,1.27) A16(-17.78,1.27) A17(-20.32,1.27) B01(20.32,-1.27) B02(17.78,-1.27) B03(15.24,-1.27) B04(12.7,-1.27) B05(10.16,-1.27) B06(7.62,-1.27) B07(5.08,-1.27) B08(2.54,-1.27) B09(0,-1.27) B10(-2.54,-1.27) B11(-5.08,-1.27) B12(-7.62,-1.27) B13(-10.16,-1.27) B14(-12.7,-1.27) B15(-15.24,-1.27) B16(-17.78,-1.27) B17(-20.32,-1.27)
PG_VG93K_F_G3D117
  round 1.778 hole 0.711: 01(-20.32,-1.27) 02(-17.78,1.27) 03(-15.24,-1.27) 04(-12.7,1.27) 05(-10.16,-1.27) 06(-7.62,1.27) 07(-5.08,-1.27) 08(-2.54,1.27) 09(0,-1.27) 10(2.54,1.27) 11(5.08,-1.27) 12(7.62,1.27) 13(10.16,-1.27) 14(12.7,1.27) 15(15.24,-1.27) 16(17.78,1.27) 17(20.32,-1.27)
  rect 1.778x1.778 hole 0.711: A1(-20.32,-3.81) A2(-17.78,-1.27) A3(-15.24,-3.81) A4(-12.7,-1.27) A5(-10.16,-3.81) A6(-7.62,-1.27) A7(-5.08,-3.81) A8(-2.54,-1.27) A9(0,-3.81) A10(2.54,-1.27) A11(5.08,-3.81) A12(7.62,-1.27) A13(10.16,-3.81) A14(12.7,-1.27) A15(15.24,-3.81) A16(17.78,-1.27) A17(20.32,-3.81) B1(-20.32,1.27) B2(-17.78,3.81) B3(-15.24,1.27) B4(-12.7,3.81) B5(-10.16,1.27) B6(-7.62,3.81) B7(-5.08,1.27) B8(-2.54,3.81) B9(0,1.27) B10(2.54,3.81) B11(5.08,1.27) B12(7.62,3.81) B13(10.16,1.27) B14(12.7,3.81) B15(15.24,1.27) B16(17.78,3.81) B17(20.32,1.27)
PG_VG93K_F_G3D118
  round 1.778 hole 0.711: 01(-20.32,-1.27) 02(-17.78,1.27) 03(-15.24,-1.27) 04(-12.7,1.27) 05(-10.16,-1.27) 06(-7.62,1.27) 07(-5.08,-1.27) 08(-2.54,1.27) 09(0,-1.27) 10(2.54,1.27) 11(5.08,-1.27) 12(7.62,1.27) 13(10.16,-1.27) 14(12.7,1.27) 15(15.24,-1.27) 16(17.78,1.27) 17(20.32,-1.27)
  rect 1.778x1.778 hole 0.711: A1(-20.32,-3.81) A2(-17.78,-1.27) A3(-15.24,-3.81) A4(-12.7,-1.27) A5(-10.16,-3.81) A6(-7.62,-1.27) A7(-5.08,-3.81) A8(-2.54,-1.27) A9(0,-3.81) A10(2.54,-1.27) A11(5.08,-3.81) A12(7.62,-1.27) A13(10.16,-3.81) A14(12.7,-1.27) A15(15.24,-3.81) A16(17.78,-1.27) A17(20.32,-3.81) B1(-20.32,1.27) B2(-17.78,3.81) B3(-15.24,1.27) B4(-12.7,3.81) B5(-10.16,1.27) B6(-7.62,3.81) B7(-5.08,1.27) B8(-2.54,3.81) B9(0,1.27) B10(2.54,3.81) B11(5.08,1.27) B12(7.62,3.81) B13(10.16,1.27) B14(12.7,3.81) B15(15.24,1.27) B16(17.78,3.81) B17(20.32,1.27)
PG_VG93K_F_G3D119
  round 1.778 hole 0.711: 01(-20.32,-1.27) 02(-17.78,1.27) 03(-15.24,-1.27) 04(-12.7,1.27) 05(-10.16,-1.27) 06(-7.62,1.27) 07(-5.08,-1.27) 08(-2.54,1.27) 09(0,-1.27) 10(2.54,1.27) 11(5.08,-1.27) 12(7.62,1.27) 13(10.16,-1.27) 14(12.7,1.27) 15(15.24,-1.27) 16(17.78,1.27) 17(20.32,-1.27)
  rect 1.778x1.778 hole 0.711: A1(-20.32,-3.81) A2(-17.78,-1.27) A3(-15.24,-3.81) A4(-12.7,-1.27) A5(-10.16,-3.81) A6(-7.62,-1.27) A7(-5.08,-3.81) A8(-2.54,-1.27) A9(0,-3.81) A10(2.54,-1.27) A11(5.08,-3.81) A12(7.62,-1.27) A13(10.16,-3.81) A14(12.7,-1.27) A15(15.24,-3.81) A16(17.78,-1.27) A17(20.32,-3.81) B1(-20.32,1.27) B2(-17.78,3.81) B3(-15.24,1.27) B4(-12.7,3.81) B5(-10.16,1.27) B6(-7.62,3.81) B7(-5.08,1.27) B8(-2.54,3.81) B9(0,1.27) B10(2.54,3.81) B11(5.08,1.27) B12(7.62,3.81) B13(10.16,1.27) B14(12.7,3.81) B15(15.24,1.27) B16(17.78,3.81) B17(20.32,1.27)
PG_VG93K_F_G3D120
  round 1.778 hole 0.711: 01(-20.32,-1.27) 02(-17.78,1.27) 03(-15.24,-1.27) 04(-12.7,1.27) 05(-10.16,-1.27) 06(-7.62,1.27) 07(-5.08,-1.27) 08(-2.54,1.27) 09(0,-1.27) 10(2.54,1.27) 11(5.08,-1.27) 12(7.62,1.27) 13(10.16,-1.27) 14(12.7,1.27) 15(15.24,-1.27) 16(17.78,1.27) 17(20.32,-1.27)
  rect 1.778x1.778 hole 0.711: A1(-20.32,-3.81) A2(-17.78,-1.27) A3(-15.24,-3.81) A4(-12.7,-1.27) A5(-10.16,-3.81) A6(-7.62,-1.27) A7(-5.08,-3.81) A8(-2.54,-1.27) A9(0,-3.81) A10(2.54,-1.27) A11(5.08,-3.81) A12(7.62,-1.27) A13(10.16,-3.81) A14(12.7,-1.27) A15(15.24,-3.81) A16(17.78,-1.27) A17(20.32,-3.81) B1(-20.32,1.27) B2(-17.78,3.81) B3(-15.24,1.27) B4(-12.7,3.81) B5(-10.16,1.27) B6(-7.62,3.81) B7(-5.08,1.27) B8(-2.54,3.81) B9(0,1.27) B10(2.54,3.81) B11(5.08,1.27) B12(7.62,3.81) B13(10.16,1.27) B14(12.7,3.81) B15(15.24,1.27) B16(17.78,3.81) B17(20.32,1.27)
PG_VG93K_F_G3D121
  round 1.778 hole 0.711: 01(-20.32,-1.27) 02(-17.78,1.27) 03(-15.24,-1.27) 04(-12.7,1.27) 05(-10.16,-1.27) 06(-7.62,1.27) 07(-5.08,-1.27) 08(-2.54,1.27) 09(0,-1.27) 10(2.54,1.27) 11(5.08,-1.27) 12(7.62,1.27) 13(10.16,-1.27) 14(12.7,1.27) 15(15.24,-1.27) 16(17.78,1.27) 17(20.32,-1.27)
  rect 1.778x1.778 hole 0.711: A1(-20.32,-3.81) A2(-17.78,-1.27) A3(-15.24,-3.81) A4(-12.7,-1.27) A5(-10.16,-3.81) A6(-7.62,-1.27) A7(-5.08,-3.81) A8(-2.54,-1.27) A9(0,-3.81) A10(2.54,-1.27) A11(5.08,-3.81) A12(7.62,-1.27) A13(10.16,-3.81) A14(12.7,-1.27) A15(15.24,-3.81) A16(17.78,-1.27) A17(20.32,-3.81) B1(-20.32,1.27) B2(-17.78,3.81) B3(-15.24,1.27) B4(-12.7,3.81) B5(-10.16,1.27) B6(-7.62,3.81) B7(-5.08,1.27) B8(-2.54,3.81) B9(0,1.27) B10(2.54,3.81) B11(5.08,1.27) B12(7.62,3.81) B13(10.16,1.27) B14(12.7,3.81) B15(15.24,1.27) B16(17.78,3.81) B17(20.32,1.27)
PG_VG93K_F_G3D122
  round 1.778 hole 0.711: 01(-20.32,-1.27) 02(-17.78,1.27) 03(-15.24,-1.27) 04(-12.7,1.27) 05(-10.16,-1.27) 06(-7.62,1.27) 07(-5.08,-1.27) 08(-2.54,1.27) 09(0,-1.27) 10(2.54,1.27) 11(5.08,-1.27) 12(7.62,1.27) 13(10.16,-1.27) 14(12.7,1.27) 15(15.24,-1.27) 16(17.78,1.27) 17(20.32,-1.27)
  rect 1.778x1.778 hole 0.711: A1(-20.32,-3.81) A2(-17.78,-1.27) A3(-15.24,-3.81) A4(-12.7,-1.27) A5(-10.16,-3.81) A6(-7.62,-1.27) A7(-5.08,-3.81) A8(-2.54,-1.27) A9(0,-3.81) A10(2.54,-1.27) A11(5.08,-3.81) A12(7.62,-1.27) A13(10.16,-3.81) A14(12.7,-1.27) A15(15.24,-3.81) A16(17.78,-1.27) A17(20.32,-3.81) B1(-20.32,1.27) B2(-17.78,3.81) B3(-15.24,1.27) B4(-12.7,3.81) B5(-10.16,1.27) B6(-7.62,3.81) B7(-5.08,1.27) B8(-2.54,3.81) B9(0,1.27) B10(2.54,3.81) B11(5.08,1.27) B12(7.62,3.81) B13(10.16,1.27) B14(12.7,3.81) B15(15.24,1.27) B16(17.78,3.81) B17(20.32,1.27)
PG_VG93K_F_G3D123
  round 1.778 hole 0.711: 01(-20.32,-1.27) 02(-17.78,1.27) 03(-15.24,-1.27) 04(-12.7,1.27) 05(-10.16,-1.27) 06(-7.62,1.27) 07(-5.08,-1.27) 08(-2.54,1.27) 09(0,-1.27) 10(2.54,1.27) 11(5.08,-1.27) 12(7.62,1.27) 13(10.16,-1.27) 14(12.7,1.27) 15(15.24,-1.27) 16(17.78,1.27) 17(20.32,-1.27)
  rect 1.778x1.778 hole 0.711: A1(-20.32,-3.81) A2(-17.78,-1.27) A3(-15.24,-3.81) A4(-12.7,-1.27) A5(-10.16,-3.81) A6(-7.62,-1.27) A7(-5.08,-3.81) A8(-2.54,-1.27) A9(0,-3.81) A10(2.54,-1.27) A11(5.08,-3.81) A12(7.62,-1.27) A13(10.16,-3.81) A14(12.7,-1.27) A15(15.24,-3.81) A16(17.78,-1.27) A17(20.32,-3.81) B1(-20.32,1.27) B2(-17.78,3.81) B3(-15.24,1.27) B4(-12.7,3.81) B5(-10.16,1.27) B6(-7.62,3.81) B7(-5.08,1.27) B8(-2.54,3.81) B9(0,1.27) B10(2.54,3.81) B11(5.08,1.27) B12(7.62,3.81) B13(10.16,1.27) B14(12.7,3.81) B15(15.24,1.27) B16(17.78,3.81) B17(20.32,1.27)
PG_VG93K_F_G3D124
  round 1.778 hole 0.711: 01(-20.32,-1.27) 02(-17.78,1.27) 03(-15.24,-1.27) 04(-12.7,1.27) 05(-10.16,-1.27) 06(-7.62,1.27) 07(-5.08,-1.27) 08(-2.54,1.27) 09(0,-1.27) 10(2.54,1.27) 11(5.08,-1.27) 12(7.62,1.27) 13(10.16,-1.27) 14(12.7,1.27) 15(15.24,-1.27) 16(17.78,1.27) 17(20.32,-1.27)
  rect 1.778x1.778 hole 0.711: A1(-20.32,-3.81) A2(-17.78,-1.27) A3(-15.24,-3.81) A4(-12.7,-1.27) A5(-10.16,-3.81) A6(-7.62,-1.27) A7(-5.08,-3.81) A8(-2.54,-1.27) A9(0,-3.81) A10(2.54,-1.27) A11(5.08,-3.81) A12(7.62,-1.27) A13(10.16,-3.81) A14(12.7,-1.27) A15(15.24,-3.81) A16(17.78,-1.27) A17(20.32,-3.81) B1(-20.32,1.27) B2(-17.78,3.81) B3(-15.24,1.27) B4(-12.7,3.81) B5(-10.16,1.27) B6(-7.62,3.81) B7(-5.08,1.27) B8(-2.54,3.81) B9(0,1.27) B10(2.54,3.81) B11(5.08,1.27) B12(7.62,3.81) B13(10.16,1.27) B14(12.7,3.81) B15(15.24,1.27) B16(17.78,3.81) B17(20.32,1.27)
PG_VG93K_F_G3DPS3
  round 1.778 hole 0.711: A01(-20.32,-2.54) A02(-17.78,-2.54) A03(-15.24,-2.54) A04(-12.7,-2.54) A05(-10.16,-2.54) A06(-7.62,-2.54) A07(-5.08,-2.54) A08(-2.54,-2.54) A09(0,-2.54) A10(2.54,-2.54) A11(5.08,-2.54) A12(7.62,-2.54) A13(10.16,-2.54) A14(12.7,-2.54) A15(15.24,-2.54) A16(17.78,-2.54) A17(20.32,-2.54) B01(-20.32,0) B02(-17.78,0) B03(-15.24,0) B04(-12.7,0) B05(-10.16,0) B06(-7.62,0) B07(-5.08,0) B08(-2.54,0) B09(0,0) B10(2.54,0) B11(5.08,0) B12(7.62,0) B13(10.16,0) B14(12.7,0) B15(15.24,0) B16(17.78,0) B17(20.32,0) C01(-20.32,2.54) C02(-17.78,2.54) C03(-15.24,2.54) C04(-12.7,2.54) C05(-10.16,2.54) C06(-7.62,2.54) C07(-5.08,2.54) C08(-2.54,2.54) C09(0,2.54) C10(2.54,2.54) C11(5.08,2.54) C12(7.62,2.54) C13(10.16,2.54) C14(12.7,2.54) C15(15.24,2.54) C16(17.78,2.54) C17(20.32,2.54)
PG_VG93K_F_G3UTI1
  round 1.778 hole 0.711: A01(-20.32,-1.27) A02(-17.78,-1.27) A03(-15.24,-1.27) A04(-12.7,-1.27) A05(-10.16,-1.27) A06(-7.62,-1.27) A07(-5.08,-1.27) A08(-2.54,-1.27) A09(0,-1.27) A10(2.54,-1.27) A11(5.08,-1.27) A12(7.62,-1.27) A13(10.16,-1.27) A14(12.7,-1.27) A15(15.24,-1.27) A16(17.78,-1.27) A17(20.32,-1.27) B01(-20.32,1.27) B02(-17.78,1.27) B03(-15.24,1.27) B04(-12.7,1.27) B05(-10.16,1.27) B06(-7.62,1.27) B07(-5.08,1.27) B08(-2.54,1.27) B09(0,1.27) B10(2.54,1.27) B11(5.08,1.27) B12(7.62,1.27) B13(10.16,1.27) B14(12.7,1.27) B15(15.24,1.27) B16(17.78,1.27) B17(20.32,1.27)
PG_VG93K_F_G8D226
  round 1.778 hole 0.711: 01(20.32,1.27) 02(17.78,-1.27) 03(15.24,1.27) 04(12.7,-1.27) 05(10.16,1.27) 06(7.62,-1.27) 07(5.08,1.27) 08(2.54,-1.27) 09(0,1.27) 10(-2.54,-1.27) 11(-5.08,1.27) 12(-7.62,-1.27) 13(-10.16,1.27) 14(-12.7,-1.27) 15(-15.24,1.27) 16(-17.78,-1.27) 17(-20.32,1.27)
  rect 1.778x1.778 hole 0.711: A1(20.32,3.81) A2(17.78,1.27) A3(15.24,3.81) A4(12.7,1.27) A5(10.16,3.81) A6(7.62,1.27) A7(5.08,3.81) A8(2.54,1.27) A9(0,3.81) A10(-2.54,1.27) A11(-5.08,3.81) A12(-7.62,1.27) A13(-10.16,3.81) A14(-12.7,1.27) A15(-15.24,3.81) A16(-17.78,1.27) A17(-20.32,3.81) B1(20.32,-1.27) B2(17.78,-3.81) B3(15.24,-1.27) B4(12.7,-3.81) B5(10.16,-1.27) B6(7.62,-3.81) B7(5.08,-1.27) B8(2.54,-3.81) B9(0,-1.27) B10(-2.54,-3.81) B11(-5.08,-1.27) B12(-7.62,-3.81) B13(-10.16,-1.27) B14(-12.7,-3.81) B15(-15.24,-1.27) B16(-17.78,-3.81) B17(-20.32,-1.27)
PG_VG93K_F_G8D227
  round 1.778 hole 0.711: 01(20.32,1.27) 02(17.78,-1.27) 03(15.24,1.27) 04(12.7,-1.27) 05(10.16,1.27) 06(7.62,-1.27) 07(5.08,1.27) 08(2.54,-1.27) 09(0,1.27) 10(-2.54,-1.27) 11(-5.08,1.27) 12(-7.62,-1.27) 13(-10.16,1.27) 14(-12.7,-1.27) 15(-15.24,1.27) 16(-17.78,-1.27) 17(-20.32,1.27)
  rect 1.778x1.778 hole 0.711: A1(20.32,3.81) A2(17.78,1.27) A3(15.24,3.81) A4(12.7,1.27) A5(10.16,3.81) A6(7.62,1.27) A7(5.08,3.81) A8(2.54,1.27) A9(0,3.81) A10(-2.54,1.27) A11(-5.08,3.81) A12(-7.62,1.27) A13(-10.16,3.81) A14(-12.7,1.27) A15(-15.24,3.81) A16(-17.78,1.27) A17(-20.32,3.81) B1(20.32,-1.27) B2(17.78,-3.81) B3(15.24,-1.27) B4(12.7,-3.81) B5(10.16,-1.27) B6(7.62,-3.81) B7(5.08,-1.27) B8(2.54,-3.81) B9(0,-1.27) B10(-2.54,-3.81) B11(-5.08,-1.27) B12(-7.62,-3.81) B13(-10.16,-1.27) B14(-12.7,-3.81) B15(-15.24,-1.27) B16(-17.78,-3.81) B17(-20.32,-1.27)
PG_VG93K_F_G8D228
  round 1.778 hole 0.711: 01(20.32,1.27) 02(17.78,-1.27) 03(15.24,1.27) 04(12.7,-1.27) 05(10.16,1.27) 06(7.62,-1.27) 07(5.08,1.27) 08(2.54,-1.27) 09(0,1.27) 10(-2.54,-1.27) 11(-5.08,1.27) 12(-7.62,-1.27) 13(-10.16,1.27) 14(-12.7,-1.27) 15(-15.24,1.27) 16(-17.78,-1.27) 17(-20.32,1.27)
  rect 1.778x1.778 hole 0.711: A1(20.32,3.81) A2(17.78,1.27) A3(15.24,3.81) A4(12.7,1.27) A5(10.16,3.81) A6(7.62,1.27) A7(5.08,3.81) A8(2.54,1.27) A9(0,3.81) A10(-2.54,1.27) A11(-5.08,3.81) A12(-7.62,1.27) A13(-10.16,3.81) A14(-12.7,1.27) A15(-15.24,3.81) A16(-17.78,1.27) A17(-20.32,3.81) B1(20.32,-1.27) B2(17.78,-3.81) B3(15.24,-1.27) B4(12.7,-3.81) B5(10.16,-1.27) B6(7.62,-3.81) B7(5.08,-1.27) B8(2.54,-3.81) B9(0,-1.27) B10(-2.54,-3.81) B11(-5.08,-1.27) B12(-7.62,-3.81) B13(-10.16,-1.27) B14(-12.7,-3.81) B15(-15.24,-1.27) B16(-17.78,-3.81) B17(-20.32,-1.27)
PG_VG93K_F_G8D230
  round 1.778 hole 0.711: 01(20.32,1.27) 02(17.78,-1.27) 03(15.24,1.27) 04(12.7,-1.27) 05(10.16,1.27) 06(7.62,-1.27) 07(5.08,1.27) 08(2.54,-1.27) 09(0,1.27) 10(-2.54,-1.27) 11(-5.08,1.27) 12(-7.62,-1.27) 13(-10.16,1.27) 14(-12.7,-1.27) 15(-15.24,1.27) 16(-17.78,-1.27) 17(-20.32,1.27)
  rect 1.778x1.778 hole 0.711: A1(20.32,3.81) A2(17.78,1.27) A3(15.24,3.81) A4(12.7,1.27) A5(10.16,3.81) A6(7.62,1.27) A7(5.08,3.81) A8(2.54,1.27) A9(0,3.81) A10(-2.54,1.27) A11(-5.08,3.81) A12(-7.62,1.27) A13(-10.16,3.81) A14(-12.7,1.27) A15(-15.24,3.81) A16(-17.78,1.27) A17(-20.32,3.81) B1(20.32,-1.27) B2(17.78,-3.81) B3(15.24,-1.27) B4(12.7,-3.81) B5(10.16,-1.27) B6(7.62,-3.81) B7(5.08,-1.27) B8(2.54,-3.81) B9(0,-1.27) B10(-2.54,-3.81) B11(-5.08,-1.27) B12(-7.62,-3.81) B13(-10.16,-1.27) B14(-12.7,-3.81) B15(-15.24,-1.27) B16(-17.78,-3.81) B17(-20.32,-1.27)
PG_VG93K_F_G8D231
  round 1.778 hole 0.711: 01(20.32,1.27) 02(17.78,-1.27) 03(15.24,1.27) 04(12.7,-1.27) 05(10.16,1.27) 06(7.62,-1.27) 07(5.08,1.27) 08(2.54,-1.27) 09(0,1.27) 10(-2.54,-1.27) 11(-5.08,1.27) 12(-7.62,-1.27) 13(-10.16,1.27) 14(-12.7,-1.27) 15(-15.24,1.27) 16(-17.78,-1.27) 17(-20.32,1.27)
  rect 1.778x1.778 hole 0.711: A1(20.32,3.81) A2(17.78,1.27) A3(15.24,3.81) A4(12.7,1.27) A5(10.16,3.81) A6(7.62,1.27) A7(5.08,3.81) A8(2.54,1.27) A9(0,3.81) A10(-2.54,1.27) A11(-5.08,3.81) A12(-7.62,1.27) A13(-10.16,3.81) A14(-12.7,1.27) A15(-15.24,3.81) A16(-17.78,1.27) A17(-20.32,3.81) B1(20.32,-1.27) B2(17.78,-3.81) B3(15.24,-1.27) B4(12.7,-3.81) B5(10.16,-1.27) B6(7.62,-3.81) B7(5.08,-1.27) B8(2.54,-3.81) B9(0,-1.27) B10(-2.54,-3.81) B11(-5.08,-1.27) B12(-7.62,-3.81) B13(-10.16,-1.27) B14(-12.7,-3.81) B15(-15.24,-1.27) B16(-17.78,-3.81) B17(-20.32,-1.27)
PG_VG93K_F_G8D232
  round 1.778 hole 0.711: 01(20.32,1.27) 02(17.78,-1.27) 03(15.24,1.27) 04(12.7,-1.27) 05(10.16,1.27) 06(7.62,-1.27) 07(5.08,1.27) 08(2.54,-1.27) 09(0,1.27) 10(-2.54,-1.27) 11(-5.08,1.27) 12(-7.62,-1.27) 13(-10.16,1.27) 14(-12.7,-1.27) 15(-15.24,1.27) 16(-17.78,-1.27) 17(-20.32,1.27)
  rect 1.778x1.778 hole 0.711: A1(20.32,3.81) A2(17.78,1.27) A3(15.24,3.81) A4(12.7,1.27) A5(10.16,3.81) A6(7.62,1.27) A7(5.08,3.81) A8(2.54,1.27) A9(0,3.81) A10(-2.54,1.27) A11(-5.08,3.81) A12(-7.62,1.27) A13(-10.16,3.81) A14(-12.7,1.27) A15(-15.24,3.81) A16(-17.78,1.27) A17(-20.32,3.81) B1(20.32,-1.27) B2(17.78,-3.81) B3(15.24,-1.27) B4(12.7,-3.81) B5(10.16,-1.27) B6(7.62,-3.81) B7(5.08,-1.27) B8(2.54,-3.81) B9(0,-1.27) B10(-2.54,-3.81) B11(-5.08,-1.27) B12(-7.62,-3.81) B13(-10.16,-1.27) B14(-12.7,-3.81) B15(-15.24,-1.27) B16(-17.78,-3.81) B17(-20.32,-1.27)
PG_VG93K_F_G8D426
  round 1.778 hole 0.711: 01(20.32,1.27) 02(17.78,-1.27) 03(15.24,1.27) 04(12.7,-1.27) 05(10.16,1.27) 06(7.62,-1.27) 07(5.08,1.27) 08(2.54,-1.27) 09(0,1.27) 10(-2.54,-1.27) 11(-5.08,1.27) 12(-7.62,-1.27) 13(-10.16,1.27) 14(-12.7,-1.27) 15(-15.24,1.27) 16(-17.78,-1.27) 17(-20.32,1.27)
  rect 1.778x1.778 hole 0.711: A1(20.32,3.81) A2(17.78,1.27) A3(15.24,3.81) A4(12.7,1.27) A5(10.16,3.81) A6(7.62,1.27) A7(5.08,3.81) A8(2.54,1.27) A9(0,3.81) A10(-2.54,1.27) A11(-5.08,3.81) A12(-7.62,1.27) A13(-10.16,3.81) A14(-12.7,1.27) A15(-15.24,3.81) A16(-17.78,1.27) A17(-20.32,3.81) B1(20.32,-1.27) B2(17.78,-3.81) B3(15.24,-1.27) B4(12.7,-3.81) B5(10.16,-1.27) B6(7.62,-3.81) B7(5.08,-1.27) B8(2.54,-3.81) B9(0,-1.27) B10(-2.54,-3.81) B11(-5.08,-1.27) B12(-7.62,-3.81) B13(-10.16,-1.27) B14(-12.7,-3.81) B15(-15.24,-1.27) B16(-17.78,-3.81) B17(-20.32,-1.27)
PG_VG93K_F_G8D427
  round 1.778 hole 0.711: 01(20.32,1.27) 02(17.78,-1.27) 03(15.24,1.27) 04(12.7,-1.27) 05(10.16,1.27) 06(7.62,-1.27) 07(5.08,1.27) 08(2.54,-1.27) 09(0,1.27) 10(-2.54,-1.27) 11(-5.08,1.27) 12(-7.62,-1.27) 13(-10.16,1.27) 14(-12.7,-1.27) 15(-15.24,1.27) 16(-17.78,-1.27) 17(-20.32,1.27)
  rect 1.778x1.778 hole 0.711: A1(20.32,3.81) A2(17.78,1.27) A3(15.24,3.81) A4(12.7,1.27) A5(10.16,3.81) A6(7.62,1.27) A7(5.08,3.81) A8(2.54,1.27) A9(0,3.81) A10(-2.54,1.27) A11(-5.08,3.81) A12(-7.62,1.27) A13(-10.16,3.81) A14(-12.7,1.27) A15(-15.24,3.81) A16(-17.78,1.27) A17(-20.32,3.81) B1(20.32,-1.27) B2(17.78,-3.81) B3(15.24,-1.27) B4(12.7,-3.81) B5(10.16,-1.27) B6(7.62,-3.81) B7(5.08,-1.27) B8(2.54,-3.81) B9(0,-1.27) B10(-2.54,-3.81) B11(-5.08,-1.27) B12(-7.62,-3.81) B13(-10.16,-1.27) B14(-12.7,-3.81) B15(-15.24,-1.27) B16(-17.78,-3.81) B17(-20.32,-1.27)
PG_VG93K_F_G8D428
  round 1.778 hole 0.711: 01(20.32,1.27) 02(17.78,-1.27) 03(15.24,1.27) 04(12.7,-1.27) 05(10.16,1.27) 06(7.62,-1.27) 07(5.08,1.27) 08(2.54,-1.27) 09(0,1.27) 10(-2.54,-1.27) 11(-5.08,1.27) 12(-7.62,-1.27) 13(-10.16,1.27) 14(-12.7,-1.27) 15(-15.24,1.27) 16(-17.78,-1.27) 17(-20.32,1.27)
  rect 1.778x1.778 hole 0.711: A1(20.32,3.81) A2(17.78,1.27) A3(15.24,3.81) A4(12.7,1.27) A5(10.16,3.81) A6(7.62,1.27) A7(5.08,3.81) A8(2.54,1.27) A9(0,3.81) A10(-2.54,1.27) A11(-5.08,3.81) A12(-7.62,1.27) A13(-10.16,3.81) A14(-12.7,1.27) A15(-15.24,3.81) A16(-17.78,1.27) A17(-20.32,3.81) B1(20.32,-1.27) B2(17.78,-3.81) B3(15.24,-1.27) B4(12.7,-3.81) B5(10.16,-1.27) B6(7.62,-3.81) B7(5.08,-1.27) B8(2.54,-3.81) B9(0,-1.27) B10(-2.54,-3.81) B11(-5.08,-1.27) B12(-7.62,-3.81) B13(-10.16,-1.27) B14(-12.7,-3.81) B15(-15.24,-1.27) B16(-17.78,-3.81) B17(-20.32,-1.27)
PG_VG93K_F_G8D430
  round 1.778 hole 0.711: 01(20.32,1.27) 02(17.78,-1.27) 03(15.24,1.27) 04(12.7,-1.27) 05(10.16,1.27) 06(7.62,-1.27) 07(5.08,1.27) 08(2.54,-1.27) 09(0,1.27) 10(-2.54,-1.27) 11(-5.08,1.27) 12(-7.62,-1.27) 13(-10.16,1.27) 14(-12.7,-1.27) 15(-15.24,1.27) 16(-17.78,-1.27) 17(-20.32,1.27)
  rect 1.778x1.778 hole 0.711: A1(20.32,3.81) A2(17.78,1.27) A3(15.24,3.81) A4(12.7,1.27) A5(10.16,3.81) A6(7.62,1.27) A7(5.08,3.81) A8(2.54,1.27) A9(0,3.81) A10(-2.54,1.27) A11(-5.08,3.81) A12(-7.62,1.27) A13(-10.16,3.81) A14(-12.7,1.27) A15(-15.24,3.81) A16(-17.78,1.27) A17(-20.32,3.81) B1(20.32,-1.27) B2(17.78,-3.81) B3(15.24,-1.27) B4(12.7,-3.81) B5(10.16,-1.27) B6(7.62,-3.81) B7(5.08,-1.27) B8(2.54,-3.81) B9(0,-1.27) B10(-2.54,-3.81) B11(-5.08,-1.27) B12(-7.62,-3.81) B13(-10.16,-1.27) B14(-12.7,-3.81) B15(-15.24,-1.27) B16(-17.78,-3.81) B17(-20.32,-1.27)
PG_VG93K_F_G8D431
  round 1.778 hole 0.711: 01(20.32,1.27) 02(17.78,-1.27) 03(15.24,1.27) 04(12.7,-1.27) 05(10.16,1.27) 06(7.62,-1.27) 07(5.08,1.27) 08(2.54,-1.27) 09(0,1.27) 10(-2.54,-1.27) 11(-5.08,1.27) 12(-7.62,-1.27) 13(-10.16,1.27) 14(-12.7,-1.27) 15(-15.24,1.27) 16(-17.78,-1.27) 17(-20.32,1.27)
  rect 1.778x1.778 hole 0.711: A1(20.32,3.81) A2(17.78,1.27) A3(15.24,3.81) A4(12.7,1.27) A5(10.16,3.81) A6(7.62,1.27) A7(5.08,3.81) A8(2.54,1.27) A9(0,3.81) A10(-2.54,1.27) A11(-5.08,3.81) A12(-7.62,1.27) A13(-10.16,3.81) A14(-12.7,1.27) A15(-15.24,3.81) A16(-17.78,1.27) A17(-20.32,3.81) B1(20.32,-1.27) B2(17.78,-3.81) B3(15.24,-1.27) B4(12.7,-3.81) B5(10.16,-1.27) B6(7.62,-3.81) B7(5.08,-1.27) B8(2.54,-3.81) B9(0,-1.27) B10(-2.54,-3.81) B11(-5.08,-1.27) B12(-7.62,-3.81) B13(-10.16,-1.27) B14(-12.7,-3.81) B15(-15.24,-1.27) B16(-17.78,-3.81) B17(-20.32,-1.27)
PG_VG93K_F_G8D432
  round 1.778 hole 0.711: 01(20.32,1.27) 02(17.78,-1.27) 03(15.24,1.27) 04(12.7,-1.27) 05(10.16,1.27) 06(7.62,-1.27) 07(5.08,1.27) 08(2.54,-1.27) 09(0,1.27) 10(-2.54,-1.27) 11(-5.08,1.27) 12(-7.62,-1.27) 13(-10.16,1.27) 14(-12.7,-1.27) 15(-15.24,1.27) 16(-17.78,-1.27) 17(-20.32,1.27)
  rect 1.778x1.778 hole 0.711: A1(20.32,3.81) A2(17.78,1.27) A3(15.24,3.81) A4(12.7,1.27) A5(10.16,3.81) A6(7.62,1.27) A7(5.08,3.81) A8(2.54,1.27) A9(0,3.81) A10(-2.54,1.27) A11(-5.08,3.81) A12(-7.62,1.27) A13(-10.16,3.81) A14(-12.7,1.27) A15(-15.24,3.81) A16(-17.78,1.27) A17(-20.32,3.81) B1(20.32,-1.27) B2(17.78,-3.81) B3(15.24,-1.27) B4(12.7,-3.81) B5(10.16,-1.27) B6(7.62,-3.81) B7(5.08,-1.27) B8(2.54,-3.81) B9(0,-1.27) B10(-2.54,-3.81) B11(-5.08,-1.27) B12(-7.62,-3.81) B13(-10.16,-1.27) B14(-12.7,-3.81) B15(-15.24,-1.27) B16(-17.78,-3.81) B17(-20.32,-1.27)
PG_VG93K_F_G8DPS8
  round 1.778 hole 0.711: A01(20.32,2.54) A02(17.78,2.54) A03(15.24,2.54) A04(12.7,2.54) A05(10.16,2.54) A06(7.62,2.54) A07(5.08,2.54) A08(2.54,2.54) A09(0,2.54) A10(-2.54,2.54) A11(-5.08,2.54) A12(-7.62,2.54) A13(-10.16,2.54) A14(-12.7,2.54) A15(-15.24,2.54) A16(-17.78,2.54) A17(-20.32,2.54) B01(20.32,0) B02(17.78,0) B03(15.24,0) B04(12.7,0) B05(10.16,0) B06(7.62,0) B07(5.08,0) B08(2.54,0) B09(0,0) B10(-2.54,0) B11(-5.08,0) B12(-7.62,0) B13(-10.16,0) B14(-12.7,0) B15(-15.24,0) B16(-17.78,0) B17(-20.32,0) C01(20.32,-2.54) C02(17.78,-2.54) C03(15.24,-2.54) C04(12.7,-2.54) C05(10.16,-2.54) C06(7.62,-2.54) C07(5.08,-2.54) C08(2.54,-2.54) C09(0,-2.54) C10(-2.54,-2.54) C11(-5.08,-2.54) C12(-7.62,-2.54) C13(-10.16,-2.54) C14(-12.7,-2.54) C15(-15.24,-2.54) C16(-17.78,-2.54) C17(-20.32,-2.54)
PG_VG93K_F_G8UTI4
  round 1.778 hole 0.711: A01(20.32,1.27) A02(17.78,1.27) A03(15.24,1.27) A04(12.7,1.27) A05(10.16,1.27) A06(7.62,1.27) A07(5.08,1.27) A08(2.54,1.27) A09(0,1.27) A10(-2.54,1.27) A11(-5.08,1.27) A12(-7.62,1.27) A13(-10.16,1.27) A14(-12.7,1.27) A15(-15.24,1.27) A16(-17.78,1.27) A17(-20.32,1.27) B01(20.32,-1.27) B02(17.78,-1.27) B03(15.24,-1.27) B04(12.7,-1.27) B05(10.16,-1.27) B06(7.62,-1.27) B07(5.08,-1.27) B08(2.54,-1.27) B09(0,-1.27) B10(-2.54,-1.27) B11(-5.08,-1.27) B12(-7.62,-1.27) B13(-10.16,-1.27) B14(-12.7,-1.27) B15(-15.24,-1.27) B16(-17.78,-1.27) B17(-20.32,-1.27)
PG_VG93K_F_HALFOUTLINE
  round 0.508 hole 3.2 unplated: (-140.276,198.12) (-140.276,102.006) (-140.276,0) (-140.276,-102.006) (-140.276,-198.12) (-73.66,157.48) (-73.66,-157.48) (7.044,198.12) (7.044,102.006) (7.044,-102.006) (7.044,-198.12) (73.66,157.48) (73.66,-157.48) (140.304,198.12) (140.304,102.006) (140.304,0) (140.304,-102.006) (140.304,-198.12)
  round 0.051 smd: GH1(70,70) GH2(-70,70) GH3(-70,-70) GH4(70,-70)
PG_VG93K_F_HSM_G1D101_501_ND
  rect 1.626x1.626 smd: A1(-20.32,-3.81) A3(-15.24,-3.81) A5(-10.16,-3.81) A7(-5.08,-3.81) A9(0,-3.81) A11(5.08,-3.81) A13(10.16,-3.81) A15(15.24,-3.81) A17(20.32,-3.81) B2(-17.78,-1.27) B4(-12.7,-1.27) B6(-7.62,-1.27) B8(-2.54,-1.27) B10(2.54,-1.27) B12(7.62,-1.27) B14(12.7,-1.27) B16(17.78,-1.27) C1(-20.32,1.27) C3(-15.24,1.27) C5(-10.16,1.27) C7(-5.08,1.27) C9(0,1.27) C11(5.08,1.27) C13(10.16,1.27) C15(15.24,1.27) C17(20.32,1.27) D2(-17.78,3.81) D4(-12.7,3.81) D6(-7.62,3.81) D8(-2.54,3.81) D10(2.54,3.81) D12(7.62,3.81) D14(12.7,3.81) D16(17.78,3.81)
  round 1.626 smd: A2(-17.78,-3.81) A4(-12.7,-3.81) A6(-7.62,-3.81) A8(-2.54,-3.81) A10(2.54,-3.81) A12(7.62,-3.81) A14(12.7,-3.81) A16(17.78,-3.81) B1(-20.32,-1.27) B3(-15.24,-1.27) B5(-10.16,-1.27) B7(-5.08,-1.27) B9(0,-1.27) B11(5.08,-1.27) B13(10.16,-1.27) B15(15.24,-1.27) B17(20.32,-1.27) C2(-17.78,1.27) C4(-12.7,1.27) C6(-7.62,1.27) C8(-2.54,1.27) C10(2.54,1.27) C12(7.62,1.27) C14(12.7,1.27) C16(17.78,1.27) D3(-15.24,3.81) D5(-10.16,3.81) D7(-5.08,3.81) D9(0,3.81) D11(5.08,3.81) D13(10.16,3.81) D15(15.24,3.81)
